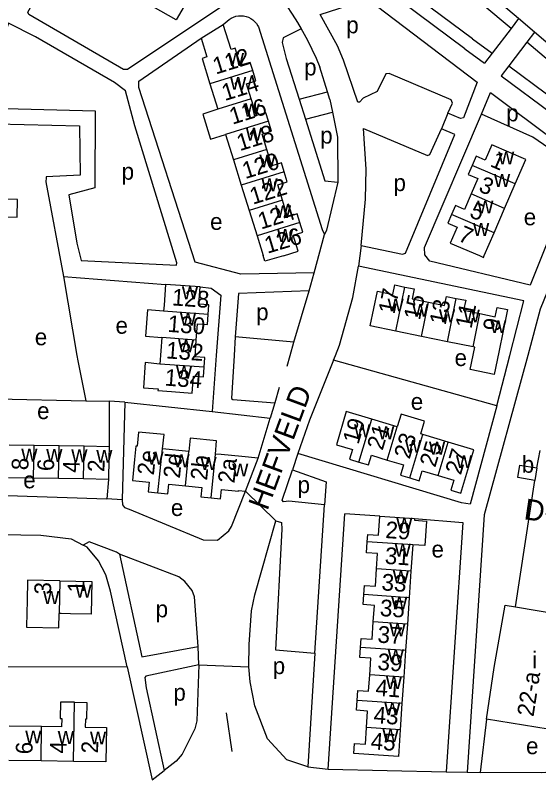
# Model space of a CAD drawing. Extents: x 163012 to 165277, y 382513 to 383987.
# Drawn here: x 164219.5 to 164344.7, y 383376 to 383557.5 of the extents above; entities that cross this region are included whole.
import ezdxf

# ---------------------------------------------------------------- set-up
doc = ezdxf.new("R2010")
doc.units = 0
for name, color, linetype in [('BLT_Basislijn', 7, 'Continuous'), ('BLT_Bebouwing', 7, 'Continuous'), ('BLT_Centroide', 7, 'Continuous'), ('BLT_Huisnummer', 7, 'Continuous'), ('BLT_Huisnummer_ tussenligend', 7, 'Continuous'), ('BLT_Huisnummer_reeks', 7, 'Continuous'), ('BLT_Onderverdeling_panden', 7, 'Continuous'), ('BLT_Straatnaam', 7, 'Continuous'), ('BLT_Vlakafsluiter', 7, 'Continuous')]:
    doc.layers.add(name, color=color, linetype=linetype)

msp = doc.modelspace()

# ---------------------------------------------------------------- linework, layer by layer
at = {"layer": 'BLT_Basislijn'}
for p, q in [((164339.89, 383556.69), (164338.06, 383554.3)), ((164338.06, 383554.3), (164333.53, 383548.41)), ((164343.7, 383553.44), (164341.87, 383551.06)), ((164341.87, 383551.06), (164337.54, 383545.43)), ((164333.53, 383548.41), (164331.7, 383546.03)), ((164294.15, 383539.21), (164292.34, 383545.11)), ((164337.54, 383545.43), (164335.71, 383543.05)), ((164287.37, 383537.42), (164294.15, 383539.21)), ((164294.71, 383537.39), (164294.15, 383539.21)), ((164331.02, 383533.86), (164333.16, 383539.03)), ((164333.16, 383539.03), (164355.14, 383522.49)), ((164287.37, 383537.42), (164288.88, 383532.65)), ((164294.71, 383537.39), (164295.34, 383534.35)), ((164288.88, 383532.65), (164295.34, 383534.35)), ((164322.97, 383534.1), (164321.43, 383530.33)), ((164290.99, 383495.91), (164293.45, 383505.08)), ((164302.23, 383502.41), (164301.6, 383497.51)), ((164289.77, 383491.62), (164290.99, 383495.91)), ((164231.07, 383495.05), (164255.45, 383493.12)), ((164286.12, 383479.33), (164289.77, 383491.62)), ((164286.12, 383479.33), (164272.1, 383480.56)), ((164285.23, 383476.11), (164286.12, 383479.33)), ((164284.52, 383473.55), (164285.23, 383476.11)), ((164334.66, 383464.11), (164295.61, 383475)), ((164282.64, 383468.45), (164281.6, 383464.81)), ((164214.14, 383465.79), (164236.37, 383465.29)), ((164236.37, 383465.29), (164241.94, 383465.16)), ((164241.94, 383465.16), (164241.93, 383454.37)), ((164245.72, 383464.94), (164241.94, 383465.16)), ((164245.72, 383464.94), (164245.09, 383441.6)), ((164245.72, 383464.94), (164266.57, 383462.68)), ((164281.6, 383464.81), (164280.46, 383461.11)), ((164266.57, 383462.68), (164280.46, 383461.11)), ((164287.11, 383452.66), (164285.78, 383448.77)), ((164344.23, 383449.24), (164345.02, 383453.37)), ((164241.81, 383446.48), (164241.41, 383441.79)), ((164339.14, 383415.95), (164343.72, 383446.22)), ((164206.05, 383443.01), (164241.41, 383441.79)), ((164245.09, 383441.6), (164241.41, 383441.79)), ((164291.14, 383404.94), (164293.45, 383440.36)), ((164294.35, 383377.16), (164298.32, 383438.27)), ((164306.69, 383437.71), (164298.32, 383438.27)), ((164315, 383437.14), (164326.51, 383436.13)), ((164326.51, 383436.13), (164322.56, 383376.53)), ((164263.4, 383402.14), (164263.28, 383406.48)), ((164291.14, 383404.94), (164289.46, 383377.68)), ((164246.24, 383401.63), (164252.27, 383374.57)), ((164269.95, 383390.66), (164271.28, 383381.41)), ((164332.17, 383389.14), (164330.66, 383376.32)), ((164289.46, 383377.68), (164294.35, 383377.16)), ((164327.57, 383376.4), (164330.66, 383376.32))]:
    msp.add_line(p, q, dxfattribs=at)
for points in [[(164273.25, 383565.1), (164271.51, 383561.46), (164246.31, 383544.54), (164245.43, 383544.51), (164222.72, 383557.67), (164222.49, 383558.28), (164230.41, 383572.21)], [(164276.68, 383569.05), (164278.34, 383567.3), (164279.94, 383565.5), (164281.49, 383563.65), (164282.97, 383561.75), (164284.38, 383559.8), (164285.73, 383557.8), (164287.02, 383555.77), (164287.89, 383554.27)], [(164328.84, 383551.9), (164309.09, 383566.65), (164307.82, 383569.05)], [(164327.04, 383549.49), (164304.52, 383566.32)], [(164292.43, 383557.65), (164303.85, 383561.46), (164330, 383541.47), (164326.71, 383533), (164326, 383532.84), (164322.97, 383534.1)], [(164339.89, 383556.69), (164333.21, 383562.36)], [(164338.06, 383554.3), (164331.34, 383560.01)], [(164269.26, 383555.3), (164270.63, 383556.49), (164271.15, 383556.82), (164271.7, 383557.08), (164272.29, 383557.26), (164272.9, 383557.37), (164273.51, 383557.4), (164274.12, 383557.35), (164274.72, 383557.22), (164275.3, 383557.01), (164275.85, 383556.73), (164276.35, 383556.38), (164276.81, 383555.97), (164277.21, 383555.5), (164277.54, 383554.99), (164277.68, 383554.73)], [(164322.97, 383534.1), (164324.03, 383536.46), (164323.74, 383537.24), (164308.89, 383543.6), (164308.12, 383543.46), (164306.07, 383539.27), (164302.69, 383537.71), (164301.8, 383536.73), (164301.43, 383536.7), (164298.02, 383546.8), (164296.56, 383550.22), (164292.43, 383557.65)], [(164243.24, 383541.42), (164224.34, 383552.38), (164217.9, 383555.62), (164211.02, 383536.22), (164210.95, 383535.33), (164238.62, 383534.61), (164238.5, 383516.21), (164232.32, 383514.58), (164234.24, 383502.99), (164235.28, 383498.8), (164258.09, 383497.72), (164258.18, 383498.3), (164248.14, 383531.09), (164245.85, 383539.41), (164243.24, 383541.42)], [(164343.7, 383553.44), (164339.89, 383556.69)], [(164277.68, 383554.73), (164292.87, 383506.26), (164293.45, 383505.08)], [(164287.89, 383554.27), (164283.61, 383552.1), (164283.3, 383551.01), (164284.28, 383547.18), (164287.37, 383537.42)], [(164287.89, 383554.27), (164288.23, 383553.69), (164289.38, 383551.57), (164290.45, 383549.41), (164291.46, 383547.22), (164292.34, 383545.11)], [(164392.82, 383515.16), (164354.55, 383544.23), (164343.7, 383553.44)], [(164290.99, 383495.91), (164273.48, 383495.57), (164262.55, 383498.42), (164249.02, 383540.24), (164249.04, 383541.77), (164263.94, 383551.99)], [(164328.84, 383551.9), (164333.53, 383548.41)], [(164390.96, 383512.81), (164352.67, 383541.89), (164341.87, 383551.06)], [(164327.04, 383549.49), (164331.7, 383546.03)], [(164337.54, 383545.43), (164373.59, 383518.63), (164396.51, 383501.2), (164414.09, 383486.88)], [(164335.71, 383543.05), (164371.79, 383516.23), (164394.66, 383498.84), (164412.16, 383484.58)], [(164295.34, 383534.35), (164296.59, 383528.32), (164296.65, 383517.56)], [(164354.3, 383520.77), (164350.68, 383513.14), (164342.61, 383492.97), (164318.64, 383498.68), (164317.46, 383500.16), (164317.37, 383501.96), (164331.02, 383533.86)], [(164354.3, 383520.77), (164343.28, 383528.32), (164331.02, 383533.86)], [(164288.88, 383532.65), (164293.56, 383517.9), (164296.65, 383517.56)], [(164214.98, 383531.5), (164234.85, 383531.03), (164235.05, 383519.27), (164226.93, 383518.88), (164226.87, 383518.63), (164226.84, 383517.64), (164231.07, 383495.05)], [(164302.23, 383502.41), (164303.23, 383513.55), (164303.44, 383520.67), (164302.8, 383530.39), (164318.1, 383523.97), (164318.64, 383524.17), (164321.43, 383530.33)], [(164302.23, 383502.41), (164312.14, 383500.32), (164312.85, 383500.57), (164324.6, 383529.01), (164321.43, 383530.33)], [(164358.45, 383520.01), (164345.06, 383487.17), (164342.05, 383476.11)], [(164296.65, 383517.56), (164293.92, 383506.11), (164293.45, 383505.08)], [(164296.06, 383476.11), (164297.07, 383478.58), (164300.25, 383490.01), (164301.6, 383497.51)], [(164337.76, 383476.11), (164341.14, 383489.21), (164301.6, 383497.51)], [(164231.07, 383495.05), (164234.25, 383476.11)], [(164263.73, 383492.52), (164266.34, 383492.26), (164268.65, 383490.58), (164267.57, 383476.11)], [(164289.77, 383491.62), (164272.91, 383490.97), (164272.1, 383480.56)], [(164272.1, 383480.56), (164271.85, 383476.11)], [(164234.25, 383476.11), (164234.46, 383474.84), (164236.37, 383465.29)], [(164267.57, 383476.11), (164266.57, 383462.68)], [(164271.85, 383476.11), (164271.25, 383465.82), (164271.52, 383465.57), (164281.6, 383464.81)], [(164295.61, 383475), (164296.06, 383476.11)], [(164342.05, 383476.11), (164331.65, 383437.97), (164327.57, 383376.4)], [(164334.66, 383464.11), (164337.76, 383476.11)], [(164295.61, 383475), (164289.91, 383460.68), (164287.11, 383452.66)], [(164334.66, 383464.11), (164328.3, 383440.51), (164326.19, 383440.85), (164287.11, 383452.66)], [(164277.57, 383451.53), (164280.46, 383461.11)], [(164293.45, 383440.36), (164284.92, 383441.24), (164283.68, 383441.12), (164283.36, 383441.47), (164285.78, 383448.77)], [(164285.78, 383448.77), (164293.88, 383445.93), (164293.45, 383440.36)], [(164245.09, 383441.6), (164245.14, 383440.39), (164245.67, 383439.77), (164246.73, 383439.32), (164264.42, 383431.99), (164267.9, 383431.97), (164270.61, 383434.14), (164271.25, 383435.19), (164274.54, 383443.63)], [(164275.37, 383401.65), (164275.41, 383406.95), (164276.03, 383415.02), (164276.83, 383418.84), (164281.83, 383436.53)], [(164281.83, 383436.53), (164283.18, 383436.18), (164283.25, 383434.59), (164281.72, 383405.7), (164291.14, 383404.94)], [(164187.08, 383433.77), (164225.61, 383433.11), (164232.85, 383432.29), (164235.71, 383430.76)], [(164244.43, 383428.59), (164243.7, 383429.09), (164237.16, 383431.52), (164235.71, 383430.76)], [(164246.24, 383401.63), (164242.29, 383419.75), (164241.19, 383423.66), (164239.42, 383426.99), (164236.68, 383430.3), (164235.71, 383430.76)], [(164244.43, 383428.59), (164249.74, 383404.02), (164263.28, 383406.48)], [(164263.28, 383406.48), (164262.4, 383418.38), (164261.85, 383419.88), (164260.08, 383422.01), (164258.66, 383423.15), (164244.43, 383428.59)], [(164187.08, 383401.73), (164246.24, 383401.63)], [(164263.4, 383402.14), (164250.76, 383399.4), (164250.52, 383399.05), (164250.81, 383396.64), (164255.1, 383376.85)], [(164263.4, 383402.14), (164262.96, 383388.73), (164262.49, 383386.81), (164259.46, 383380.76), (164258.02, 383379.1), (164255.1, 383376.85)], [(164289.46, 383377.68), (164284.49, 383379.41), (164279.86, 383384.42), (164276.83, 383392.3), (164275.7, 383398.03), (164275.37, 383401.65)], [(164252.27, 383374.57), (164255.1, 383376.85)], [(164294.35, 383377.16), (164322.56, 383376.53)], [(164322.56, 383376.53), (164327.57, 383376.4)], [(164359.07, 383377.33), (164345.39, 383376.28), (164330.66, 383376.32)]]:
    msp.add_lwpolyline(points, dxfattribs=at)
at = {"layer": 'BLT_Bebouwing'}
for p, q in [((164263.94, 383551.99), (164269.26, 383555.3)), ((164266.06, 383541.12), (164267.93, 383535.05)), ((164269.81, 383528.99), (164271.69, 383522.92)), ((164271.69, 383522.92), (164273.56, 383516.85)), ((164336.53, 383511.3), (164339.05, 383517.16)), ((164273.56, 383516.85), (164275.44, 383510.78)), ((164275.44, 383510.78), (164277.32, 383504.72)), ((164334, 383505.44), (164336.53, 383511.3)), ((164277.32, 383504.72), (164278.78, 383500)), ((164331.66, 383500), (164334, 383505.44)), ((164263.73, 383492.52), (164255.45, 383493.12)), ((164316.69, 383480.67), (164310.55, 383481.92)), ((164254.54, 383480.42), (164254.08, 383474.07)), ((164322.84, 383479.41), (164316.69, 383480.67)), ((164328.99, 383478.15), (164322.84, 383479.41)), ((164310.86, 383459.04), (164304.77, 383460.87)), ((164323.05, 383455.38), (164316.95, 383457.21)), ((164218.02, 383454.74), (164223.99, 383454.65)), ((164223.99, 383454.65), (164229.97, 383454.55)), ((164229.97, 383454.55), (164235.95, 383454.47)), ((164235.95, 383454.47), (164241.93, 383454.37)), ((164261.03, 383453.18), (164254.68, 383453.81)), ((164340.2, 383449.91), (164344.23, 383449.24)), ((164344.23, 383449.24), (164343.72, 383446.22)), ((164223.88, 383446.75), (164217.9, 383446.84)), ((164229.85, 383446.66), (164223.88, 383446.75)), ((164235.83, 383446.57), (164229.85, 383446.66)), ((164241.81, 383446.48), (164235.83, 383446.57)), ((164306.69, 383437.71), (164315, 383437.14)), ((164314.57, 383430.82), (164314.14, 383424.5)), ((164314.14, 383424.5), (164313.71, 383418.17)), ((164313.71, 383418.17), (164313.28, 383411.85)), ((164339.14, 383415.95), (164354.11, 383413.46)), ((164313.28, 383411.85), (164312.85, 383405.52)), ((164312.85, 383405.52), (164312.42, 383399.19)), ((164312.42, 383399.19), (164311.99, 383392.87)), ((164311.99, 383392.87), (164311.56, 383386.54)), ((164225.82, 383387.36), (164218.08, 383387.48)), ((164225.7, 383379.14), (164217.96, 383379.25)), ((164233.44, 383379.02), (164225.7, 383379.14))]:
    msp.add_line(p, q, dxfattribs=at)
for points in [[(164256.64, 383566.77), (164259.93, 383564.88), (164261, 383566.74), (164263.23, 383565.47), (164258.01, 383556.38), (164252.49, 383559.55)], [(164276.29, 383544.29), (164275.69, 383546.24), (164273.4, 383545.54), (164272.12, 383549.65), (164271.1, 383549.33), (164269.26, 383555.3)], [(164263.94, 383551.99), (164265.32, 383547.54), (164264.18, 383547.19), (164266.06, 383541.12)], [(164275.93, 383537.53), (164274.83, 383541.09), (164277.07, 383541.78), (164276.29, 383544.29)], [(164280.03, 383532.15), (164279.4, 383534.17), (164277.18, 383533.49), (164275.93, 383537.53)], [(164267.93, 383535.05), (164264.35, 383533.88), (164266.22, 383527.84), (164269.81, 383528.99)], [(164279.69, 383525.4), (164278.56, 383529.06), (164280.77, 383529.74), (164280.03, 383532.15)], [(164339.05, 383517.16), (164341.58, 383523.02), (164333.44, 383526.52), (164331.86, 383522.85), (164329.71, 383523.77), (164328.77, 383521.59)], [(164283.84, 383520.03), (164283.18, 383522.17), (164280.9, 383521.47), (164279.69, 383525.4)], [(164328.77, 383521.59), (164327.84, 383519.41), (164330.09, 383518.44), (164328.51, 383514.76)], [(164283.4, 383513.25), (164282.26, 383516.95), (164284.57, 383517.66), (164283.84, 383520.03)], [(164214.67, 383507.59), (164214.69, 383509.27), (164219.96, 383509.19), (164220.02, 383513.44), (164214.75, 383513.56)], [(164328.51, 383514.76), (164326.9, 383511.03), (164324.75, 383511.96), (164323.83, 383509.83)], [(164287.58, 383507.89), (164286.92, 383509.99), (164284.63, 383509.29), (164283.4, 383513.25)], [(164323.83, 383509.83), (164322.94, 383507.77), (164325.18, 383506.8), (164323.55, 383503), (164330.51, 383500)], [(164283.65, 383499.98), (164287.17, 383501.07), (164285.99, 383504.89), (164288.28, 383505.6), (164287.58, 383507.89)], [(164283.65, 383499.98), (164279.2, 383498.65), (164278.78, 383500)], [(164330.51, 383500), (164331.48, 383499.58), (164331.66, 383500)], [(164255.45, 383493.12), (164255.09, 383488.13), (164254.99, 383486.73)], [(164265.63, 383485.93), (164265.77, 383488.2), (164263.43, 383488.36), (164263.73, 383492.52)], [(164310.55, 383481.92), (164304.4, 383483.18), (164306.1, 383491.5), (164309.81, 383490.74), (164310.27, 383492.98), (164312.7, 383492.49)], [(164312.7, 383492.49), (164314.91, 383492.03), (164314.42, 383489.65), (164318.36, 383488.84)], [(164318.36, 383488.84), (164322.15, 383488.07), (164322.6, 383490.26), (164324.96, 383489.78)], [(164324.96, 383489.78), (164327.22, 383489.32), (164326.74, 383486.93), (164330.62, 383486.14)], [(164254.99, 383486.73), (164251.14, 383487.01), (164250.67, 383480.72), (164254.54, 383480.42)], [(164330.62, 383486.14), (164334.29, 383485.39), (164334.74, 383487.62), (164337.22, 383487.11), (164335.13, 383476.9), (164334.04, 383471.57), (164328.31, 383472.74), (164329.4, 383478.07), (164328.99, 383478.15)], [(164262.79, 383479.82), (164263.07, 383483.72), (164265.46, 383483.55), (164265.63, 383485.93)], [(164264.67, 383473.3), (164264.84, 383475.61), (164262.5, 383475.78), (164262.79, 383479.82)], [(164254.08, 383474.07), (164250.59, 383474.4), (164250.15, 383468.35), (164253.65, 383468.1), (164253.62, 383467.72), (164256.85, 383467.49), (164261.83, 383467.13), (164262.13, 383471.2), (164264.51, 383471.03), (164264.67, 383473.3)], [(164304.77, 383460.87), (164298.67, 383462.7), (164296.29, 383454.78), (164300.12, 383453.63), (164299.42, 383451.31), (164301.69, 383450.62)], [(164316.95, 383457.21), (164316.47, 383457.35), (164317.38, 383460.38), (164311.79, 383462.06), (164310.86, 383459.04)], [(164254.68, 383453.81), (164255.09, 383457.21), (164249, 383457.81), (164248.66, 383454.41), (164248.34, 383454.44), (164248.02, 383451.22), (164247.52, 383446.24), (164251.49, 383445.85), (164251.26, 383443.52), (164253.64, 383443.28)], [(164267.38, 383452.55), (164267.64, 383455.71), (164261.35, 383456.34), (164261.03, 383453.18)], [(164241.93, 383454.37), (164241.89, 383451.48), (164241.81, 383446.48)], [(164320.65, 383447.4), (164324.4, 383446.27), (164323.69, 383443.92), (164326.04, 383443.22), (164329.14, 383453.55), (164323.05, 383455.38)], [(164277.57, 383451.53), (164273.73, 383451.92), (164268.75, 383452.41), (164267.38, 383452.55)], [(164301.69, 383450.62), (164304.02, 383449.92), (164304.72, 383452.24), (164308.48, 383451.11)], [(164274.54, 383443.63), (164277.57, 383451.53)], [(164308.48, 383451.11), (164312.36, 383449.95), (164311.63, 383447.52), (164313.84, 383446.85)], [(164313.84, 383446.85), (164316.1, 383446.17), (164316.82, 383448.55), (164320.65, 383447.4)], [(164343.72, 383446.22), (164339.69, 383446.9), (164340.2, 383449.91)], [(164253.64, 383443.28), (164255.99, 383443.05), (164256.21, 383445.33), (164260.21, 383444.93)], [(164260.21, 383444.93), (164264.12, 383444.54), (164263.89, 383442.28), (164266.33, 383442.04)], [(164266.33, 383442.04), (164268.6, 383441.81), (164268.82, 383444.09), (164272.91, 383443.68), (164272.92, 383443.79), (164274.54, 383443.63)], [(164303.68, 383431.56), (164303.8, 383433.28), (164306.38, 383433.1), (164306.69, 383437.71)], [(164315, 383437.14), (164314.97, 383436.69), (164317.85, 383436.5), (164317.45, 383430.63), (164314.57, 383430.82)], [(164305.91, 383425.06), (164306.15, 383428.72), (164303.5, 383428.9), (164303.68, 383431.56)], [(164302.88, 383418.91), (164303.03, 383421.11), (164305.63, 383420.94), (164305.91, 383425.06)], [(164230.14, 383422.19), (164222.45, 383422.35), (164222.34, 383417.35), (164222.29, 383414.6), (164222.22, 383411.15), (164229.91, 383410.99), (164229.98, 383414.4)], [(164230.14, 383422.19), (164237.84, 383422.03), (164237.68, 383414.24), (164232.68, 383414.34), (164230.51, 383414.39), (164229.98, 383414.4)], [(164305.13, 383412.4), (164305.4, 383416.34), (164302.71, 383416.52), (164302.88, 383418.91)], [(164332.17, 383389.14), (164334.07, 383401.47), (164336.67, 383416.36), (164339.14, 383415.95)], [(164302.1, 383406.25), (164302.25, 383408.43), (164304.85, 383408.25), (164305.13, 383412.4)], [(164304.28, 383399.74), (164304.36, 383400.9), (164304.55, 383403.68), (164301.93, 383403.85), (164302.1, 383406.25)], [(164301.26, 383393.6), (164301.42, 383395.95), (164304.01, 383395.78), (164304.28, 383399.74)], [(164233.65, 383393.16), (164231.62, 383393.19), (164230.34, 383393.21), (164230.28, 383389.29), (164230.62, 383389.28), (164230.59, 383387.29), (164225.82, 383387.36)], [(164233.65, 383393.16), (164236.62, 383393.12), (164236.56, 383389.1), (164236.28, 383389.1), (164236.26, 383387.18), (164241.3, 383387.1), (164241.18, 383378.91), (164233.44, 383379.02)], [(164303.5, 383387.09), (164303.77, 383391.05), (164301.1, 383391.24), (164301.26, 383393.6)], [(164350.64, 383390.69), (164349.88, 383386.21), (164332.17, 383389.14)], [(164300.49, 383380.94), (164300.65, 383383.33), (164303.23, 383383.15), (164303.5, 383387.09)], [(164311.56, 383386.54), (164311.14, 383380.22), (164300.49, 383380.94)]]:
    msp.add_lwpolyline(points, dxfattribs=at)
at = {"layer": 'BLT_Onderverdeling_panden'}
for p, q in [((164276.29, 383544.29), (164266.06, 383541.12)), ((164275.93, 383537.53), (164267.93, 383535.05)), ((164280.03, 383532.15), (164269.81, 383528.99)), ((164279.69, 383525.4), (164271.69, 383522.92)), ((164339.05, 383517.16), (164328.77, 383521.59)), ((164283.84, 383520.03), (164273.56, 383516.85)), ((164336.53, 383511.3), (164328.51, 383514.76)), ((164283.4, 383513.25), (164275.44, 383510.78)), ((164334, 383505.44), (164323.83, 383509.83)), ((164287.58, 383507.89), (164277.32, 383504.72)), ((164310.55, 383481.92), (164312.7, 383492.49)), ((164316.69, 383480.67), (164318.36, 383488.84)), ((164322.84, 383479.41), (164324.96, 383489.78)), ((164265.63, 383485.93), (164254.99, 383486.73)), ((164328.99, 383478.15), (164330.62, 383486.14)), ((164262.79, 383479.82), (164254.54, 383480.42)), ((164264.67, 383473.3), (164254.08, 383474.07)), ((164301.69, 383450.62), (164304.77, 383460.87)), ((164308.48, 383451.11), (164310.86, 383459.04)), ((164313.84, 383446.85), (164316.95, 383457.21)), ((164223.88, 383446.75), (164223.99, 383454.65)), ((164229.85, 383446.66), (164229.97, 383454.55)), ((164235.83, 383446.57), (164235.95, 383454.47)), ((164253.64, 383443.28), (164254.68, 383453.81)), ((164320.65, 383447.4), (164323.05, 383455.38)), ((164260.21, 383444.93), (164261.03, 383453.18)), ((164266.33, 383442.04), (164267.38, 383452.55)), ((164314.57, 383430.82), (164303.68, 383431.56)), ((164314.14, 383424.5), (164305.91, 383425.06)), ((164230.14, 383422.19), (164229.98, 383414.4)), ((164313.71, 383418.17), (164302.88, 383418.91)), ((164313.28, 383411.85), (164305.13, 383412.4)), ((164312.85, 383405.52), (164302.1, 383406.25)), ((164312.42, 383399.19), (164304.28, 383399.74)), ((164233.44, 383379.02), (164233.65, 383393.16)), ((164311.99, 383392.87), (164301.26, 383393.6)), ((164225.7, 383379.14), (164225.82, 383387.36)), ((164311.56, 383386.54), (164303.5, 383387.09))]:
    msp.add_line(p, q, dxfattribs=at)
at = {"layer": 'BLT_Vlakafsluiter'}
for p, q in [((164274.54, 383443.63), (164281.83, 383436.53)), ((164263.4, 383402.14), (164275.37, 383401.65))]:
    msp.add_line(p, q, dxfattribs=at)

# ---------------------------------------------------------------- texts
at = {"layer": 'BLT_Centroide'}
for s, p in [('p', (164298.66, 383553.19)), ('w', (164270.34, 383545.38)), ('p', (164288.59, 383543.11)), ('w', (164270.88, 383539.69)), ('w', (164274.09, 383533.25)), ('p', (164336.92, 383532.13)), ('w', (164274.65, 383527.53)), ('p', (164292.43, 383526.8)), ('w', (164334.98, 383521.84)), ('w', (164277.88, 383521.12)), ('p', (164244.95, 383518.16)), ('w', (164333.99, 383516.44)), ('w', (164278.38, 383515.41)), ('p', (164309.96, 383515.45)), ('w', (164281.62, 383508.97)), ('w', (164329.98, 383510.09)), ('e', (164341.11, 383507.26)), ('e', (164266.1, 383506.16)), ('w', (164282.13, 383503.28)), ('w', (164328.98, 383504.72)), ('w', (164259.36, 383489.56)), ('w', (164308.55, 383486.67)), ('w', (164314.45, 383485.38)), ('w', (164258.89, 383483.28)), ('p', (164277.11, 383484.54)), ('w', (164320.83, 383484.08)), ('w', (164326.73, 383484.02)), ('w', (164333.09, 383481.47)), ('e', (164243.48, 383481.32)), ('e', (164224.18, 383478.56)), ('w', (164258.43, 383476.88)), ('e', (164324.57, 383473.59)), ('w', (164257.95, 383470.59)), ('e', (164314.09, 383463.11)), ('e', (164224.73, 383460.9)), ('w', (164300.53, 383456.55)), ('w', (164306.28, 383456.09)), ('w', (164312.72, 383452.83)), ('w', (164318.45, 383452.41)), ('w', (164220.95, 383450.73)), ('w', (164226.92, 383450.64)), ('w', (164232.91, 383450.56)), ('w', (164238.88, 383450.47)), ('w', (164251.11, 383450.02)), ('w', (164257.33, 383449.38)), ('w', (164263.8, 383448.73)), ('w', (164324.89, 383449.19)), ('b', (164340.63, 383448.06)), ('w', (164271.38, 383447.19)), ('e', (164221.42, 383444.34)), ('p', (164287.02, 383443.2)), ('e', (164256.72, 383437.72)), ('w', (164310.62, 383434.25)), ('w', (164310.24, 383428.03)), ('e', (164319.05, 383427.79)), ('w', (164309.8, 383421.62)), ('w', (164233.91, 383418.22)), ('w', (164226.17, 383416.67)), ('w', (164309.42, 383415.38)), ('p', (164253.08, 383413.48)), ('w', (164308.99, 383408.97)), ('w', (164308.57, 383402.72)), ('i', (164343.14, 383401.3)), ('p', (164281.08, 383399.9)), ('w', (164308.14, 383396.31)), ('p', (164257.32, 383393.53)), ('w', (164307.75, 383390.06)), ('w', (164307.32, 383383.66)), ('w', (164221.89, 383383.31)), ('w', (164229.67, 383383.19)), ('w', (164237.38, 383383.06)), ('e', (164341.66, 383380.74))]:
    msp.add_text(s, height=4, dxfattribs=at).set_placement(p)
at = {"layer": 'BLT_Huisnummer'}
for s, rotation, p in [('112', 17.1951, (164267.45, 383543.31)), ('116', 17.1949, (164271.43, 383531.31)), ('120', 17.1937, (164274.51, 383518.31)), ('1', 336.6885, (164332.85, 383521.45)), ('126', 16.7063, (164279.81, 383500.45)), ('7', 336.6903, (164325.16, 383503.67)), ('128', 355.8845, (164256.86, 383488.12)), ('17', 78.4524, (164310.18, 383485.85)), ('13', 78.4533, (164322.41, 383483.24)), ('9', 78.4583, (164335.18, 383481.68)), ('134', 355.8841, (164255.14, 383468.93)), ('19', 73.29, (164301.55, 383454.68)), ('23', 73.2891, (164313.8, 383451.15)), ('27', 73.2916, (164326.05, 383447.36)), ('2e', 84.3135, (164252.65, 383447.37)), ('2d', 84.3135, (164258.87, 383446.62)), ('2b', 84.3213, (164265.37, 383446.15)), ('6', 89.1293, (164228.77, 383448.44)), ('2', 89.1292, (164240.83, 383448.23)), ('2a', 84.3239, (164271.92, 383445.44)), ('29', 356.12, (164307.93, 383432.46)), ('33', 356.1203, (164307.01, 383419.94)), ('3', 88.8306, (164228.05, 383418.9)), ('1', 88.8232, (164236.01, 383419.35)), ('37', 356.1226, (164306.04, 383407.45)), ('41', 356.1162, (164305.56, 383394.71)), ('45', 356.1173, (164304.42, 383381.93)), ('6', 89.1363, (164223.63, 383380.7)), ('2', 89.1401, (164239.31, 383380.91))]:
    msp.add_text(s, height=4, rotation=rotation, dxfattribs=at).set_placement(p)
at = {"layer": 'BLT_Huisnummer_ tussenligend'}
for s, rotation, p in [('114', 17.1951, (164269.61, 383536.97)), ('118', 17.1949, (164273.21, 383524.98)), ('122', 17.1937, (164276.31, 383512.17)), ('3', 336.6885, (164330.07, 383515.49)), ('124', 17.1937, (164278.27, 383506.23)), ('5', 336.6885, (164327.89, 383509.35)), ('15', 78.4533, (164316.27, 383484.42)), ('11', 78.4583, (164328.59, 383482.37)), ('130', 355.8845, (164255.86, 383481.78)), ('132', 355.8845, (164255.48, 383475.44)), ('21', 73.29, (164307.34, 383453.25)), ('25', 73.2891, (164319.93, 383449.17)), ('8', 89.1293, (164222.64, 383448.65)), ('4', 89.1292, (164234.89, 383448.02)), ('31', 356.12, (164307.79, 383426.29)), ('35', 356.1203, (164306.62, 383413.8)), ('39', 356.1226, (164306.05, 383400.91)), ('43', 356.1162, (164305.11, 383388.2)), ('4', 89.1401, (164231.79, 383380.89))]:
    msp.add_text(s, height=4, rotation=rotation, dxfattribs=at).set_placement(p)
at = {"layer": 'BLT_Huisnummer_reeks'}
msp.add_text('22-a', height=4, rotation=81.3244, dxfattribs=at).set_placement((164343.44, 383389.59))
at = {"layer": 'BLT_Straatnaam'}
for s, rotation, p in [('HEFVELD', 69.762, (164279.81, 383438.84)), ('DOORNAKKERSWEG', 351.7938, (164340.97, 383436.97))]:
    msp.add_text(s, height=5, rotation=rotation, dxfattribs=at).set_placement(p)

doc.saveas('drawing.dxf')
